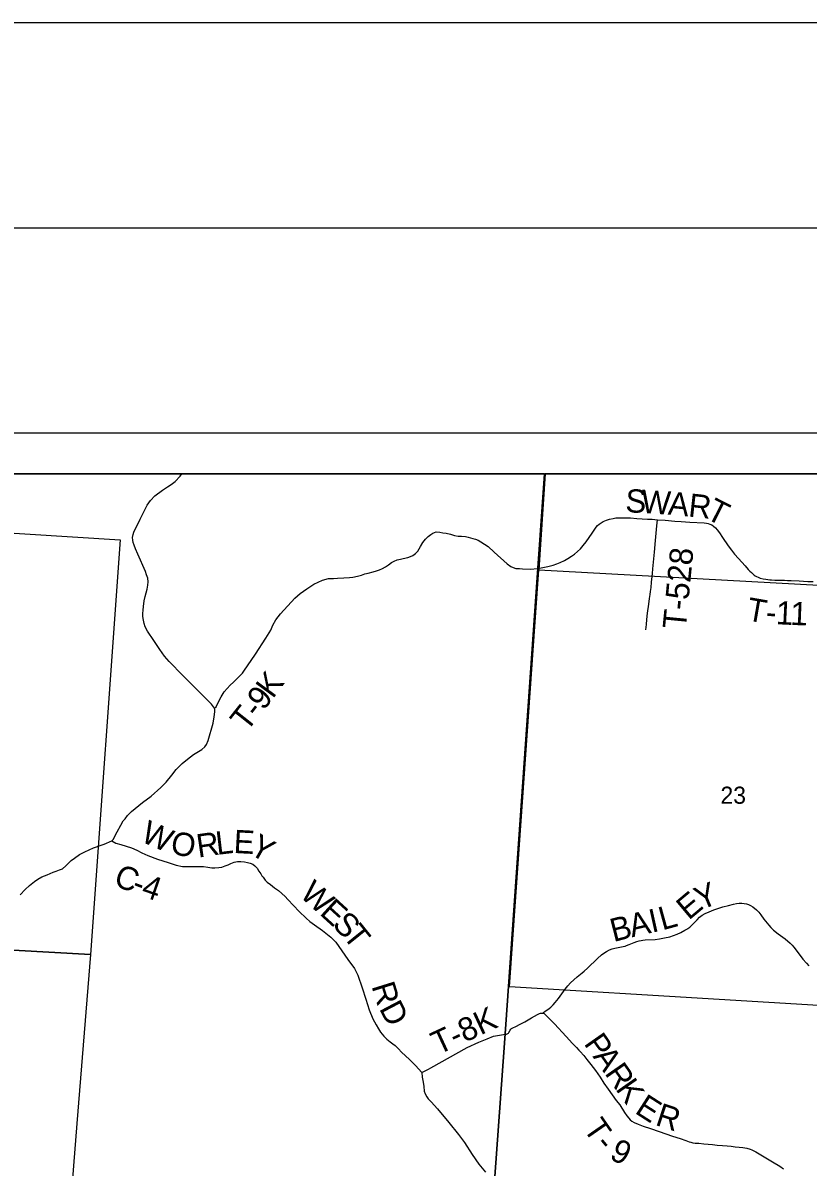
# Model space of a CAD drawing. Extents: x 0 to 34, y 0 to 22.
# Drawn here: x 5.404 to 7.32, y 19.209 to 22 of the extents above; entities that cross this region are included whole.
import ezdxf

# ---------------------------------------------------------------- set-up
doc = ezdxf.new("R2010")
doc.units = 0
for name, color, linetype in [('GM_X_Corporation', 7, 'Continuous'), ('GM_X_County_Road', 7, 'Continuous'), ('GM_X_County_Road_Text', 7, 'Continuous'), ('GM_X_Section_Text', 7, 'Continuous'), ('GM_X_State_Route', 7, 'Continuous'), ('GM_X_Township_Road', 7, 'Continuous'), ('GM_X_Township_Road_Text', 7, 'Continuous'), ('GM_X_Township_Text', 7, 'Continuous'), ('SH_Border', 7, 'Continuous'), ('SH_Cut_Line', 7, 'Continuous'), ('SH_Data', 7, 'Continuous')]:
    doc.layers.add(name, color=color, linetype=linetype)

msp = doc.modelspace()

# ---------------------------------------------------------------- linework, layer by layer
at = {"layer": 'GM_X_Corporation'}
msp.add_lwpolyline([(6.4774, 18.0202), (6.488, 18.1751), (6.5242, 18.7061), (6.5297, 18.7882), (6.5448, 18.981), (6.5455, 18.9878), (6.5461, 19.0017), (6.5463, 19.0089), (6.5469, 19.0218), (6.548, 19.0466), (6.5487, 19.0617), (6.5495, 19.082), (6.5503, 19.0966), (6.5514, 19.1091), (6.5523, 19.1179), (6.5529, 19.1264), (6.5537, 19.1382), (6.5541, 19.1447), (6.5536, 19.1514), (6.5814, 19.5334), (6.6608, 20.6694), (6.6768, 20.9), (2.1, 20.9), (2.1, 14.1)], dxfattribs=at)
for points in [[(7.7078, 20.9), (6.6786, 20.9), (6.6629, 20.6653), (7.6877, 20.6095)], [(5.6414, 20.7385), (5.5693, 19.7272), (4.5379, 19.7849), (4.607, 20.8038)], [(6.6629, 20.6653), (7.6877, 20.6095), (7.6147, 19.5863), (6.5914, 19.6486)], [(4.5379, 19.7849), (5.5693, 19.7272), (5.5363, 19.3151), (5.5032, 18.9017), (5.4857, 18.6848), (4.465, 18.749)]]:
    msp.add_lwpolyline(points, close=True, dxfattribs=at)
at = {"layer": 'GM_X_County_Road'}
msp.add_lwpolyline([(5.6216, 20.0043), (5.6311, 19.999), (5.6434, 19.9954), (5.6692, 19.9876), (5.6821, 19.9819), (5.6942, 19.9755), (5.709, 19.9688), (5.7329, 19.9599), (5.7585, 19.9514), (5.7787, 19.9455), (5.7937, 19.9419), (5.8043, 19.9415), (5.8191, 19.9417), (5.8322, 19.9423), (5.8452, 19.9417), (5.8553, 19.9402), (5.8651, 19.9389), (5.8727, 19.9389), (5.8824, 19.9395), (5.8898, 19.9406), (5.8981, 19.9432), (5.9049, 19.9457), (5.9118, 19.9491), (5.9199, 19.9527), (5.9277, 19.9539), (5.9358, 19.9544), (5.9453, 19.9529), (5.9521, 19.9514), (5.9591, 19.9497), (5.965, 19.9472), (5.9703, 19.9438), (5.9756, 19.9381), (5.98, 19.9309), (5.9849, 19.9239), (5.9874, 19.9192), (5.9904, 19.9156), (5.9955, 19.9084), (6.0003, 19.9036), (6.0084, 19.8976), (6.0183, 19.8898), (6.0281, 19.8832), (6.0444, 19.8686), (6.0505, 19.8618), (6.0787, 19.832), (6.0954, 19.8159), (6.1045, 19.8081), (6.116, 19.7998), (6.135, 19.7854), (6.1558, 19.7695), (6.168, 19.7577), (6.1973, 19.7147), (6.2131, 19.6929), (6.2212, 19.6764), (6.232, 19.6455), (6.2415, 19.6179), (6.2493, 19.5919), (6.2578, 19.5703), (6.2661, 19.5553), (6.2718, 19.5455), (6.2773, 19.5379), (6.2851, 19.5282), (6.2925, 19.5207), (6.3004, 19.5142), (6.3067, 19.5095), (6.3127, 19.5051), (6.3207, 19.497), (6.3281, 19.489), (6.3476, 19.471), (6.3622, 19.4564), (6.3774, 19.4396), (6.3789, 19.428), (6.3813, 19.4161), (6.3823, 19.4051), (6.3834, 19.3939), (6.3855, 19.3869), (6.3897, 19.3802), (6.3933, 19.3751), (6.4003, 19.3679), (6.4158, 19.3507), (6.4439, 19.3173), (6.467, 19.2878), (6.4822, 19.2684), (6.5002, 19.2389), (6.5166, 19.2154), (6.5329, 19.1959)], dxfattribs=at)
at = {"layer": 'GM_X_State_Route'}
msp.add_lwpolyline([(5.3975, 19.8729), (5.4096, 19.8858), (5.4204, 19.8957), (5.4325, 19.9055), (5.4405, 19.9112), (5.4509, 19.9165), (5.4632, 19.9216), (5.4784, 19.9277), (5.4858, 19.9307), (5.4935, 19.9336), (5.5009, 19.9364), (5.5093, 19.9438), (5.5223, 19.9569), (5.5303, 19.9624), (5.5424, 19.9711), (5.5557, 19.9777), (5.5765, 19.9872), (5.6027, 19.9967), (5.6216, 20.0043), (5.6242, 20.0074), (5.634, 20.0268), (5.6429, 20.0424), (5.6491, 20.0533), (5.6537, 20.0584), (5.6599, 20.0662), (5.6694, 20.076), (5.6964, 20.0979), (5.7177, 20.1137), (5.7412, 20.1348), (5.7538, 20.1478), (5.7681, 20.1647), (5.7783, 20.1786), (5.7928, 20.1935), (5.8056, 20.2041), (5.8205, 20.2149), (5.8408, 20.2271), (5.8479, 20.2337), (5.8522, 20.2393), (5.8566, 20.249), (5.8682, 20.2915), (5.8713, 20.3067), (5.8724, 20.3193), (5.873, 20.3251), (5.8721, 20.328), (5.8647, 20.3378), (5.8464, 20.356), (5.8205, 20.3821), (5.7946, 20.4076), (5.761, 20.4424), (5.7499, 20.4553), (5.7387, 20.4711), (5.7239, 20.4932), (5.7082, 20.5158), (5.7028, 20.527), (5.7005, 20.5351), (5.6989, 20.5432), (5.6972, 20.5519), (5.6968, 20.5593), (5.6976, 20.5672), (5.6984, 20.5765), (5.7001, 20.5902), (5.7028, 20.6004), (5.7074, 20.6188), (5.7094, 20.628), (5.7098, 20.636), (5.709, 20.6452), (5.7063, 20.6537), (5.7038, 20.6613), (5.6848, 20.704), (5.679, 20.7169), (5.6756, 20.7262), (5.6736, 20.732), (5.6723, 20.7382), (5.6721, 20.7447), (5.6732, 20.7517), (5.6754, 20.7575), (5.6906, 20.7892), (5.7074, 20.8231), (5.7156, 20.8349), (5.726, 20.846), (5.7447, 20.8597), (5.7575, 20.8678), (5.7662, 20.8738), (5.7758, 20.8813), (5.7878, 20.8945), (5.7922, 20.9)], dxfattribs=at)
at = {"layer": 'GM_X_Township_Road'}
for points in [[(6.661, 20.6689), (6.6772, 20.6724), (6.6856, 20.6741), (6.6985, 20.6773), (6.7071, 20.68), (6.7152, 20.6833), (6.7255, 20.6886), (6.7342, 20.6937), (6.7429, 20.6991), (6.7506, 20.7041), (6.7579, 20.7106), (6.7648, 20.7172), (6.7713, 20.7247), (6.7785, 20.734), (6.793, 20.7555), (6.803, 20.7695), (6.8066, 20.7736), (6.8106, 20.7773), (6.815, 20.7805), (6.8204, 20.7834), (6.8283, 20.7868), (6.8353, 20.7891), (6.8443, 20.7912), (6.8509, 20.7922), (6.8614, 20.7927), (6.8731, 20.7927), (6.8799, 20.7925), (6.8867, 20.7922), (6.9021, 20.7912), (6.9284, 20.7895), (6.9398, 20.7889), (6.9528, 20.7878), (6.9718, 20.7866), (6.9953, 20.7846), (7.0107, 20.7833), (7.0318, 20.7819), (7.0666, 20.78), (7.0721, 20.7795), (7.0768, 20.7787), (7.0808, 20.7773), (7.0851, 20.7751), (7.0895, 20.772), (7.0941, 20.768), (7.0986, 20.7629), (7.1042, 20.7556), (7.1117, 20.7449), (7.1255, 20.7243), (7.1331, 20.7137), (7.1409, 20.7039), (7.1503, 20.6931), (7.1665, 20.6751), (7.1742, 20.6662), (7.1782, 20.6622), (7.1819, 20.6589), (7.1867, 20.6545), (7.1884, 20.653), (7.1911, 20.6514), (7.1947, 20.6492), (7.1988, 20.6474), (7.2034, 20.6457), (7.2106, 20.6439), (7.2171, 20.6425), (7.2222, 20.642), (7.2272, 20.6414), (7.2309, 20.6411), (7.239, 20.6407), (7.247, 20.6405), (7.2538, 20.6405), (7.2592, 20.6403), (7.2623, 20.6402), (7.2697, 20.6399), (7.279, 20.6396), (7.2982, 20.6386), (7.3193, 20.6374), (7.3323, 20.6368)], [(6.9244, 20.5194), (6.9256, 20.5324), (6.9269, 20.5447), (6.9288, 20.5601), (6.9317, 20.5816), (6.9336, 20.5957), (6.9349, 20.6056), (6.9358, 20.613), (6.9371, 20.6228), (6.9385, 20.6356), (6.94, 20.6491), (6.9407, 20.6565), (6.9418, 20.6682), (6.9453, 20.7091), (6.9482, 20.7375), (6.9514, 20.7727), (6.9528, 20.7878)], [(5.8721, 20.328), (5.876, 20.3318), (5.8802, 20.3403), (5.8883, 20.356), (5.8956, 20.3678), (5.9028, 20.3765), (5.9101, 20.3846), (5.918, 20.3915), (5.9312, 20.4049), (5.9399, 20.4134), (5.9434, 20.4182), (5.9723, 20.4599), (5.9973, 20.4986), (6.0092, 20.5185), (6.0141, 20.5305), (6.0212, 20.5434), (6.0328, 20.5581), (6.068, 20.5965), (6.0807, 20.6076), (6.0971, 20.6197), (6.1145, 20.6304), (6.1354, 20.6404), (6.1497, 20.6445), (6.1623, 20.6449), (6.1723, 20.645), (6.1876, 20.646), (6.2013, 20.6466), (6.2094, 20.6476), (6.2204, 20.6503), (6.2309, 20.653), (6.2388, 20.6557), (6.2467, 20.6576), (6.2594, 20.6609), (6.2674, 20.6634), (6.2745, 20.6657), (6.2821, 20.669), (6.2888, 20.6731), (6.2964, 20.6781), (6.3035, 20.6835), (6.3105, 20.687), (6.3174, 20.6903), (6.3257, 20.692), (6.3325, 20.6935), (6.3435, 20.6961), (6.3503, 20.6978), (6.3562, 20.7009), (6.3622, 20.7051), (6.368, 20.7115), (6.3744, 20.7223), (6.3798, 20.7322), (6.387, 20.7407), (6.3935, 20.7473), (6.3995, 20.7517), (6.4047, 20.755), (6.4131, 20.7585), (6.4218, 20.7579), (6.4289, 20.7563), (6.4372, 20.755), (6.4478, 20.7523), (6.4571, 20.7496), (6.4664, 20.7476), (6.4749, 20.7474), (6.484, 20.7469), (6.4909, 20.7457), (6.5025, 20.7424), (6.5089, 20.7407), (6.5153, 20.738), (6.5218, 20.7343), (6.54, 20.7225), (6.5543, 20.7088), (6.5862, 20.68), (6.5953, 20.6738), (6.6007, 20.6713), (6.6072, 20.6692), (6.6159, 20.6686), (6.6231, 20.6684), (6.6418, 20.6671), (6.661, 20.6689)], [(7.027, 19.7908), (7.0317, 19.7943), (7.0368, 19.7988), (7.0495, 19.8119), (7.0556, 19.8179), (7.0621, 19.8229), (7.0688, 19.827), (7.0788, 19.8313), (7.0901, 19.8358), (7.1123, 19.8432), (7.1264, 19.8471), (7.1383, 19.8501), (7.1455, 19.8513), (7.1522, 19.8522), (7.1586, 19.8523), (7.1644, 19.8518), (7.1696, 19.8506), (7.175, 19.849), (7.1799, 19.8468), (7.1858, 19.8433), (7.194, 19.8361), (7.1997, 19.8302), (7.2046, 19.8239), (7.2124, 19.8138), (7.2245, 19.7989), (7.2294, 19.7933), (7.2362, 19.7869), (7.2475, 19.778), (7.2645, 19.7652), (7.2763, 19.7552), (7.2816, 19.75), (7.2856, 19.7453), (7.2958, 19.7313), (7.3076, 19.7161), (7.316, 19.7062), (7.3223, 19.6995)], [(6.6731, 19.5843), (6.6751, 19.5862), (6.6775, 19.588), (6.6883, 19.5955), (6.6927, 19.5991), (6.6979, 19.6041), (6.7035, 19.6103), (6.7111, 19.6202), (6.7275, 19.6429), (6.7337, 19.6506), (6.7404, 19.6579), (6.7485, 19.6657), (6.7565, 19.6725), (6.7687, 19.6822), (6.7739, 19.6866), (6.7822, 19.6941), (6.8064, 19.7173), (6.8164, 19.7266), (6.8218, 19.7307), (6.8282, 19.7346), (6.8354, 19.7383), (6.8418, 19.7408), (6.8489, 19.7428), (6.8605, 19.7451), (6.869, 19.7466), (6.8737, 19.7479), (6.8774, 19.7491), (6.884, 19.7514), (6.8957, 19.7565), (6.9025, 19.7588), (6.9082, 19.7605), (6.9128, 19.7617), (6.9168, 19.7621), (6.923, 19.7627), (6.9469, 19.7639), (6.958, 19.7653), (6.9702, 19.7675), (6.9829, 19.7705), (6.9918, 19.7732), (7.0005, 19.7766), (7.01, 19.781), (7.0199, 19.7863), (7.0262, 19.7902), (7.027, 19.7908)], [(6.5816, 19.5329), (6.584, 19.5332), (6.5858, 19.5338), (6.5876, 19.5345), (6.5893, 19.5356), (6.5903, 19.5369), (6.5935, 19.5429), (6.5949, 19.545), (6.5969, 19.5467), (6.6002, 19.5484), (6.607, 19.5517), (6.6176, 19.557), (6.6293, 19.5633), (6.6456, 19.5724), (6.6602, 19.5806), (6.6646, 19.5829), (6.6671, 19.5838), (6.6694, 19.5843), (6.6718, 19.5844), (6.6731, 19.5843), (6.6747, 19.5838), (6.6763, 19.5832), (6.6778, 19.582), (6.6879, 19.5719), (6.6926, 19.5669), (6.7012, 19.558), (6.7299, 19.527), (6.7456, 19.5103), (6.7495, 19.5063), (6.7551, 19.5004), (6.761, 19.4941), (6.7639, 19.4908), (6.7728, 19.4805), (6.7802, 19.4713), (6.7899, 19.459), (6.8013, 19.4439), (6.8126, 19.4276), (6.8222, 19.4133), (6.8322, 19.3986), (6.8523, 19.3713), (6.8606, 19.3602), (6.8725, 19.3418), (6.8782, 19.3333), (6.8825, 19.328), (6.8863, 19.3239), (6.8905, 19.3206), (6.8956, 19.3176), (6.9053, 19.3134), (6.9175, 19.3088), (6.9355, 19.3025), (6.9572, 19.295), (6.9895, 19.2842), (7.0079, 19.278), (7.022, 19.2732), (7.0299, 19.2705), (7.0343, 19.269), (7.0391, 19.2681), (7.0447, 19.2673), (7.0538, 19.2667), (7.0655, 19.2657), (7.0874, 19.2635), (7.0981, 19.2624), (7.1112, 19.2614), (7.1224, 19.2604), (7.1323, 19.2594), (7.1421, 19.2584), (7.152, 19.2574), (7.1613, 19.2563), (7.1704, 19.2545), (7.1793, 19.2519), (7.1828, 19.2505), (7.1928, 19.2456), (7.2091, 19.2361), (7.2209, 19.229), (7.2338, 19.2214), (7.251, 19.2105), (7.2606, 19.2042)], [(6.3774, 19.4396), (6.3872, 19.4443), (6.394, 19.4477), (6.3999, 19.4504), (6.4882, 19.5006), (6.5172, 19.5135), (6.5373, 19.5216), (6.553, 19.5282), (6.5816, 19.5329)]]:
    msp.add_lwpolyline(points, dxfattribs=at)
at = {"layer": 'GM_X_Township_Text'}
msp.add_lwpolyline([(6.6768, 20.9), (6.6608, 20.6694), (6.5814, 19.5334), (6.5536, 19.1514), (6.5541, 19.1447), (6.5537, 19.1382), (6.5529, 19.1264), (6.5523, 19.1179), (6.5514, 19.1091), (6.5503, 19.0966), (6.5495, 19.082), (6.5487, 19.0617), (6.548, 19.0466), (6.5469, 19.0218), (6.5463, 19.0089), (6.5461, 19.0017), (6.5455, 18.9878), (6.5448, 18.981), (6.5297, 18.7882), (6.5242, 18.7061), (6.488, 18.1751), (6.4774, 18.0202)], dxfattribs=at)
at = {"layer": 'SH_Border'}
msp.add_lwpolyline([(1.5, 21.5), (33.5, 21.5), (33.5, 0.5), (1.5, 0.5)], close=True, dxfattribs=at)
at = {"layer": 'SH_Cut_Line'}
msp.add_lwpolyline([(0, 0), (34, 0), (34, 22), (0, 22)], close=True, dxfattribs=at)
at = {"layer": 'SH_Data'}
for p, q in [((2, 21), (9, 21)), ((2.1, 20.9), (8.9, 20.9))]:
    msp.add_line(p, q, dxfattribs=at)

# ---------------------------------------------------------------- texts
at = {"layer": 'GM_X_County_Road_Text'}
for s, rotation, p in [('W', 336.4603, (5.689, 20.0042)), ('O', 348.5138, (5.7618, 19.974)), ('R', 8.3616, (5.8322, 19.9635)), ('L', 6.6838, (5.8779, 19.9702)), ('E', 356.9214, (5.9176, 19.975)), ('Y', 330.2565, (5.9534, 19.9747)), ('C', 338.5907, (5.6229, 19.897)), ('4', 340.91, (5.6905, 19.8708)), ('W', 317.8359, (6.0773, 19.8704)), ('-', 339.1165, (5.6669, 19.8797)), ('E', 317.6675, (6.1261, 19.8263)), ('S', 314.58, (6.1569, 19.7982)), ('T', 308.882, (6.1828, 19.772)), ('R', 287.2858, (6.2545, 19.6503)), ('D', 297.6697, (6.2726, 19.5956))]:
    msp.add_text(s, height=0.0568, rotation=rotation, dxfattribs=at).set_placement(p)
at = {"layer": 'GM_X_Section_Text'}
msp.add_text('23', height=0.04186, rotation=0, dxfattribs=at).set_placement((7.1065, 20.0949))
at = {"layer": 'GM_X_Township_Road_Text'}
for s, height, rotation, p in [('S', 0.0568, 357.4667, (6.8737, 20.8063)), ('W', 0.0568, 356.3262, (6.9117, 20.8046)), ('A', 0.0568, 354.7396, (6.977, 20.8004)), ('R', 0.0568, 353.8094, (7.0265, 20.7959)), ('T', 0.0568, 333.0555, (7.0677, 20.7924)), ('T-528', 0.05682, 84.4613, (7.0217, 20.5196)), ('T', 0.0568, 350.1114, (7.1679, 20.5429)), ('1', 0.0568, 357.1865, (7.2407, 20.5331)), ('1', 0.0568, 357.7129, (7.2762, 20.5314)), ('-', 0.0568, 355.939, (7.2161, 20.5349)), ('K', 0.0568, 53.6258, (6.0141, 20.3494)), ('9', 0.0568, 52.0956, (5.9916, 20.3205)), ('T', 0.0568, 51.6119, (5.9504, 20.2684)), ('-', 0.0568, 51.7292, (5.9769, 20.3019)), ('Y', 0.0568, 22.5083, (7.0577, 19.8343)), ('E', 0.0568, 39.9063, (7.029, 19.8094)), ('B', 0.0568, 14.3931, (6.8455, 19.7574)), ('A', 0.0568, 12.9954, (6.8903, 19.7689)), ('I', 0.0568, 12.5424, (6.9389, 19.7801)), ('L', 0.0568, 15.3793, (6.9647, 19.7859)), ('T-8K', 0.05682, 24.8977, (6.4175, 19.4816)), ('P', 0.0568, 304.9671, (6.7717, 19.5099)), ('A', 0.0568, 304.9663, (6.7937, 19.4785)), ('R', 0.0568, 304.9663, (6.8224, 19.4375)), ('K', 0.0568, 304.9689, (6.8491, 19.3992)), ('E', 0.0568, 327.3093, (6.8951, 19.3416)), ('R', 0.0568, 341.8344, (6.9451, 19.3119)), ('T', 0.0568, 304.7206, (6.7701, 19.3027)), ('-', 0.0568, 310.3135, (6.7979, 19.263)), ('9', 0.0568, 333.8314, (6.833, 19.2297))]:
    msp.add_text(s, height=height, rotation=rotation, dxfattribs=at).set_placement(p)

doc.saveas('drawing.dxf')
